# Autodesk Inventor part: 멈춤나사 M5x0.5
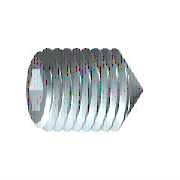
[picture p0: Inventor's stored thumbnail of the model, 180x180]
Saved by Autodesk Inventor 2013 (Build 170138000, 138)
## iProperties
Company: 한국ATC센터
IsCustomPart: 1
Created: 2014-10
Part Number: 멈춤나사 M5x0.5
Material: 강, 연강
Description: 6각 소켓 머리 없는 멈춤 나사
Document SubType Name: Modeling
Standard: KS B 1028
Designer: 한국ATC센터
Standards Organization: KS
Language: ko-KR
Size Designation: 원추점 M5x10
Categories: <MemberInstance><Categories><Category DisplayName="조임쇠" InternalName="e4da775c-781d-43d5-af7c-5136215cf5a6" Mnemonic="FSTN"><Category DisplayName="볼트" InternalN
Density: 7.86 g/cm^3
Mass: 1.16912 g
Surface Area: 1.91683 cm^2
Volume: 0.148743 cm^3
Author: KYOUNG IL JANG
Revision Number: 1
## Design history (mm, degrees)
sketch "스케치1"
  geometry: L1 (0, 0)-(6.167, 0); L2 (10, 1.443)-(10, 2.5); L3 (10, 2.5)-(0, 2.5); L4 (10, 1.443)-(7, 1.443); L5 (7, 1.443)-(6.167, 0); L6 (0, -0.5)-(0, 3) reference; L7 (0, 2.5)-(0, 0)
  constraints: 13 end point, 3 parallel, 1 collinear, 1 perpendicular, 1 point on line
  dimensions: "d0" = 3 distance of L2.start L4.end (= INTI); "d1" = 60 deg angle of L5 L1; "d2" = 5 diameter of L3 L1 (= NND); "d3" = 2.88675 diameter of L4 L1 (= 1.1547 x SW); "d5" = 10 distance from line of L2 L3.end (= NLG)
revolve "본체" sketch "스케치1" stored, may be unused: angle "d6" = 90 deg
sketch "스케치2"
  geometry: L1 (-0.722, 1.25)-(0.722, 1.25); L2 (0.722, 1.25)-(1.443, 0); L3 (1.443, 0)-(0.722, -1.25); L4 (0.722, -1.25)-(-0.722, -1.25); L5 (-0.722, -1.25)-(-1.443, 0); L6 (-1.443, 0)-(-0.722, 1.25); 3 further points
  constraints: 12 end point, 1 coincident, 1 horizontal, 13 other
extrude "슬롯" join sketch "스케치2" taper "d7" = 0 deg; stored distance "d21" = 10
workaxis "Work Axis1"
workplane "Work Plane1"
body "Solid1"
feature "스레드" dims "d12" = 10 (= NLG), "d13" = 0
chamfer "모따기1" distance "d8" = 2.25 (computed from NND, SPD, FAWI); stored, may be unused: angle "d9" = 45 deg (= FAWI), second distance "d34" = 2.25 (computed from NND, SPD, FAWI)
chamfer "모따기2" distance "d10" = 0.49076 (= -0.5 x GD1 + 0.5 x NND); stored, may be unused: angle "d11" = 45 deg (= FAWI), second distance "d35" = 0.49076 (= -0.5 x GD1 + 0.5 x NND)
other parameters: "NND" = 5 [user parameter; used in 5 equation terms], "NLG" = 10 [user parameter; used in 2 equation terms], "INTI" = 3 [user parameter; used in 1 equation term], "FAWI" = 45 deg [user parameter; used in 4 equation terms], "SW" = 2.5 [user parameter; used in 2 equation terms], "GD1" = 4.01848 (= THREADDIA - 1.2269 x PTC) [user parameter; used in 2 equation terms], "d4" = 0, "FAWI1" = 45 deg [user parameter], "SPD" = 0.5 [user parameter; used in 2 equation terms], "d36" = 0, "d37" = 0, "GUL" = 0.49076 (= 0.61345 x PTC) [user parameter], "TPU" = 12.5 (computed from PTC) [user parameter], "TOA" = 30 deg [user parameter], "THREADDIA" = 5 [user parameter; used in 1 equation term], "PTC" = 0.8 [user parameter; used in 4 equation terms], "GAL" = 0.49076 (= 0.61345 x PTC) [user parameter], "E0" = 2.8875 (= 1.155 x SW) [user parameter]
